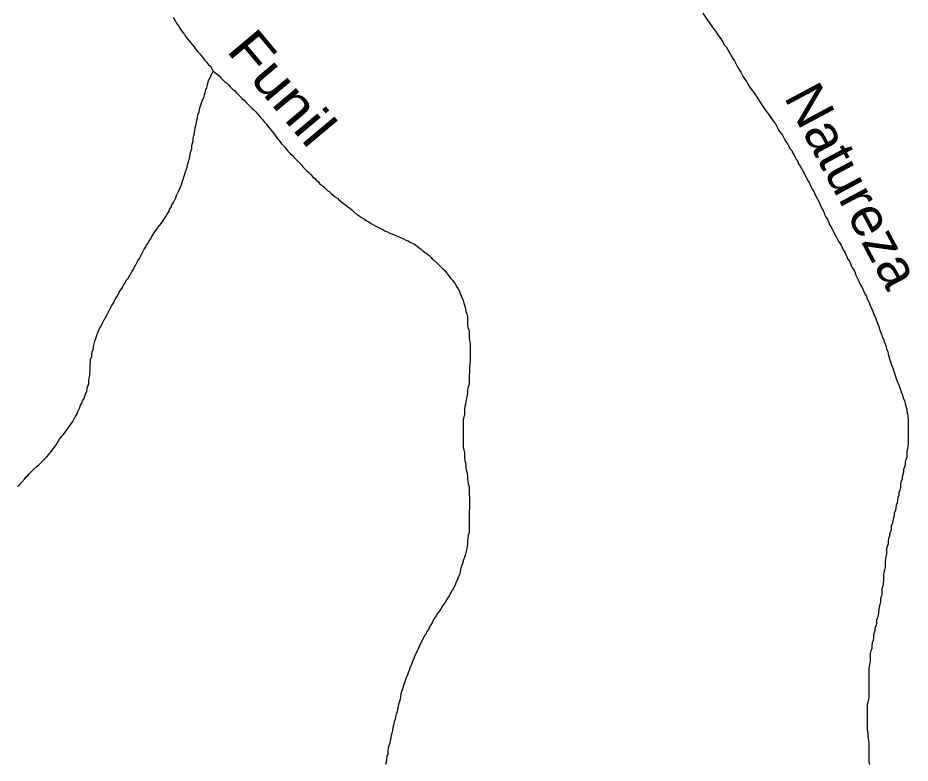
# Model space of a CAD drawing. Extents: x 652.3 to 678, y 7316.9 to 7344.9.
# Drawn here: x 663.889 to 665.722, y 7328.056 to 7329.588 of the extents above; entities that cross this region are included whole.
import ezdxf
from ezdxf.enums import TextEntityAlignment as Align

# ---------------------------------------------------------------- set-up
doc = ezdxf.new("R2010")
doc.units = 0
doc.header["$LTSCALE"] = 0.032
doc.layers.add('61', color=7, linetype='Continuous')
doc.layers.add('7', color=7, linetype='Continuous', lineweight=25)

msp = doc.modelspace()

# ---------------------------------------------------------------- linework, layer by layer
at = {"layer": '7'}
for points in [[(665.2961, 7329.5979), (665.3056, 7329.5836), (665.3088, 7329.5788), (665.312, 7329.574), (665.3152, 7329.57), (665.3184, 7329.5653), (665.3215, 7329.5613), (665.3279, 7329.5517), (665.3311, 7329.547), (665.3375, 7329.5374), (665.3398, 7329.5326), (665.3438, 7329.5287), (665.3462, 7329.5239), (665.3494, 7329.5191), (665.3518, 7329.5143), (665.355, 7329.5096), (665.3574, 7329.5048), (665.3605, 7329.5), (665.3653, 7329.4905), (665.3685, 7329.4857), (665.3709, 7329.4809), (665.3741, 7329.4769), (665.3788, 7329.4674), (665.382, 7329.4626), (665.3852, 7329.4578), (665.3876, 7329.4531), (665.394, 7329.4435), (665.3971, 7329.4387), (665.4003, 7329.4348), (665.4099, 7329.4204), (665.4131, 7329.4157), (665.4226, 7329.4014), (665.4258, 7329.3966), (665.429, 7329.3926), (665.4321, 7329.3886), (665.4353, 7329.3838), (665.4417, 7329.3743), (665.4449, 7329.3703), (665.4497, 7329.3608), (665.4528, 7329.356), (665.456, 7329.3512), (665.4592, 7329.3472), (665.464, 7329.3377), (665.4672, 7329.3329), (665.4703, 7329.3289), (665.4727, 7329.3242), (665.4751, 7329.3194), (665.4783, 7329.3154), (665.4799, 7329.3106), (665.4831, 7329.3067), (665.4878, 7329.2971), (665.491, 7329.2931), (665.4926, 7329.2884), (665.4958, 7329.2836), (665.4982, 7329.2788), (665.5014, 7329.274), (665.5038, 7329.2693), (665.5109, 7329.2549), (665.5141, 7329.2502), (665.5165, 7329.2454), (665.5181, 7329.2406), (665.5213, 7329.2358), (665.5237, 7329.2311), (665.526, 7329.2263), (665.5276, 7329.2215), (665.5308, 7329.2168), (665.5332, 7329.212)], [(664.2076, 7329.5899), (664.21, 7329.5852), (664.2132, 7329.5804), (664.2155, 7329.5756), (664.2187, 7329.5716), (664.2211, 7329.5669), (664.2243, 7329.5629), (664.2275, 7329.5581), (664.2307, 7329.5541), (664.2338, 7329.5493), (664.237, 7329.5454), (664.2402, 7329.5414), (664.2434, 7329.5374), (664.2466, 7329.5334), (664.2498, 7329.5295), (664.2529, 7329.5255), (664.2561, 7329.5215), (664.2593, 7329.5175), (664.2633, 7329.5135), (664.2665, 7329.5088), (664.2696, 7329.5048), (664.2728, 7329.5008), (664.2768, 7329.4968), (664.28, 7329.4921)], [(664.28, 7329.4921), (664.284, 7329.4889), (664.2895, 7329.4785)], [(664.2084, 7329.2088), (664.2132, 7329.2183), (664.2147, 7329.2231), (664.2195, 7329.2327), (664.2211, 7329.2374), (664.2235, 7329.2422), (664.2251, 7329.2478), (664.2267, 7329.2526), (664.2315, 7329.2669), (664.233, 7329.2717), (664.2362, 7329.2812), (664.237, 7329.2868), (664.2394, 7329.2923), (664.2402, 7329.2979), (664.2418, 7329.3027), (664.2426, 7329.3091), (664.2442, 7329.3138), (664.2458, 7329.3194), (664.2458, 7329.3258), (664.2474, 7329.3305), (664.249, 7329.3353), (664.249, 7329.3409), (664.2498, 7329.3464), (664.2513, 7329.3512), (664.2521, 7329.3568), (664.2529, 7329.3624), (664.2545, 7329.3671), (664.2553, 7329.3727), (664.2561, 7329.3783), (664.2577, 7329.3831), (664.2585, 7329.3894), (664.2609, 7329.3942), (664.2617, 7329.4006), (664.2633, 7329.4053), (664.2681, 7329.4197), (664.2704, 7329.4244), (664.272, 7329.43), (664.2736, 7329.4348), (664.2744, 7329.4403), (664.2768, 7329.4451), (664.2784, 7329.4507), (664.28, 7329.4594), (664.284, 7329.4674), (664.2895, 7329.4785)], [(664.2895, 7329.4785), (664.3023, 7329.469), (664.3055, 7329.465), (664.3094, 7329.461), (664.3134, 7329.4578), (664.3174, 7329.4547), (664.3214, 7329.4507), (664.3253, 7329.4459), (664.3293, 7329.4419), (664.3333, 7329.4387), (664.3373, 7329.4348), (664.3413, 7329.4308), (664.3452, 7329.4268), (664.3492, 7329.4228), (664.3532, 7329.4189), (664.3572, 7329.4149), (664.3612, 7329.4109), (664.3651, 7329.4069), (664.3691, 7329.4029), (664.3731, 7329.399), (664.3771, 7329.395), (664.381, 7329.391), (664.3842, 7329.387), (664.3874, 7329.3831), (664.3914, 7329.3791), (664.3946, 7329.3743), (664.3986, 7329.3703), (664.4017, 7329.3663), (664.4049, 7329.3624), (664.4081, 7329.3584), (664.4113, 7329.3544), (664.4145, 7329.3504), (664.4176, 7329.3457), (664.4208, 7329.3417), (664.424, 7329.3377), (664.4272, 7329.3337), (664.4304, 7329.3297), (664.4336, 7329.3258), (664.4375, 7329.3218), (664.4407, 7329.3178), (664.4439, 7329.3138), (664.4479, 7329.3098), (664.4519, 7329.3059), (664.4558, 7329.3019), (664.4598, 7329.2979), (664.4638, 7329.2939), (664.467, 7329.29), (664.471, 7329.286), (664.4741, 7329.282), (664.4781, 7329.278), (664.4821, 7329.274), (664.4861, 7329.2701), (664.4901, 7329.2661), (664.494, 7329.2621), (664.498, 7329.2589), (664.5012, 7329.2549), (664.5052, 7329.2518), (664.5084, 7329.2478), (664.5123, 7329.2446), (664.5163, 7329.2414), (664.5203, 7329.2374), (664.5243, 7329.2343), (664.5282, 7329.2311), (664.5322, 7329.2271), (664.5362, 7329.2239), (664.5402, 7329.2207), (664.545, 7329.2175), (664.5489, 7329.2136), (664.5537, 7329.2104), (664.5577, 7329.2064), (664.5625, 7329.2032), (664.5664, 7329.2), (664.5704, 7329.1969), (664.5744, 7329.1937), (664.5784, 7329.1905), (664.5824, 7329.1865), (664.5871, 7329.1833), (664.5919, 7329.1802), (664.5959, 7329.177), (664.6007, 7329.1746), (664.6046, 7329.1714), (664.6094, 7329.169), (664.6142, 7329.1658), (664.619, 7329.1626), (664.6237, 7329.1603), (664.6285, 7329.1579), (664.6333, 7329.1555), (664.6381, 7329.1531), (664.6428, 7329.1507), (664.6476, 7329.1483), (664.6524, 7329.1459), (664.6571, 7329.1443), (664.6619, 7329.142), (664.6667, 7329.1404), (664.6715, 7329.138), (664.6762, 7329.1364), (664.681, 7329.134), (664.6858, 7329.1316), (664.6906, 7329.13)], [(663.8885, 7328.6253), (663.8887, 7328.6256), (663.8909, 7328.6279), (663.902, 7328.6399), (663.9052, 7328.6439), (663.9092, 7328.6478), (663.9124, 7328.6518), (663.9164, 7328.6558), (663.9203, 7328.659), (663.9283, 7328.6669), (663.9323, 7328.6701), (663.9482, 7328.686), (663.9514, 7328.69), (663.9546, 7328.694), (663.9641, 7328.7059), (663.9673, 7328.7107), (663.9697, 7328.7155), (663.9729, 7328.7202), (663.9792, 7328.7282), (663.9824, 7328.7322), (663.9856, 7328.737), (663.9888, 7328.7417), (663.9983, 7328.7537), (664.0015, 7328.7584), (664.0063, 7328.768), (664.0095, 7328.7728), (664.011, 7328.7775), (664.0158, 7328.7871), (664.0174, 7328.7919), (664.0198, 7328.7966), (664.0214, 7328.8014), (664.0246, 7328.8062), (664.0262, 7328.811), (664.0278, 7328.8157), (664.0301, 7328.8205), (664.0309, 7328.8269), (664.0341, 7328.8364), (664.0341, 7328.842), (664.0349, 7328.8476), (664.0365, 7328.8531), (664.0365, 7328.8587), (664.0373, 7328.8643), (664.0373, 7328.8754), (664.0381, 7328.881), (664.0381, 7328.8865), (664.0405, 7328.8913), (664.0405, 7328.8969), (664.0413, 7328.9025), (664.0437, 7328.9072), (664.0437, 7328.9128), (664.0469, 7328.9239), (664.0484, 7328.9295), (664.05, 7328.9343), (664.0532, 7328.9438), (664.0556, 7328.9486), (664.058, 7328.9534), (664.0612, 7328.9582), (664.066, 7328.9677), (664.0683, 7328.9725), (664.0715, 7328.9772), (664.0763, 7328.9868), (664.0787, 7328.9916), (664.0811, 7328.9963), (664.0843, 7329.0011), (664.0866, 7329.0059), (664.089, 7329.0107), (664.0922, 7329.0146), (664.0946, 7329.0194), (664.097, 7329.0242), (664.1033, 7329.0337), (664.1057, 7329.0385), (664.1089, 7329.0433), (664.1113, 7329.0481), (664.1145, 7329.052), (664.1169, 7329.0568), (664.1201, 7329.0616), (664.1224, 7329.0664), (664.1256, 7329.0703), (664.1272, 7329.0751), (664.1304, 7329.0791), (664.1352, 7329.0886), (664.1384, 7329.0934), (664.1455, 7329.1077), (664.1479, 7329.1125), (664.1511, 7329.1165), (664.1527, 7329.1213), (664.1559, 7329.1252), (664.1583, 7329.13), (664.1614, 7329.134), (664.1638, 7329.1388), (664.1702, 7329.1483), (664.1734, 7329.1531), (664.1766, 7329.1579), (664.1829, 7329.1658), (664.1925, 7329.1802), (664.1956, 7329.1849), (664.1988, 7329.1897), (664.2004, 7329.1945), (664.2036, 7329.1992), (664.2052, 7329.204), (664.2084, 7329.2088)], [(665.5332, 7329.212), (665.5356, 7329.2072), (665.5372, 7329.2024), (665.5396, 7329.1977), (665.5427, 7329.1921), (665.5451, 7329.1873), (665.5467, 7329.1825), (665.5491, 7329.1778), (665.5523, 7329.173), (665.5547, 7329.1674), (665.5563, 7329.1626), (665.5595, 7329.1587), (665.5666, 7329.1443), (665.569, 7329.1396), (665.5738, 7329.13), (665.577, 7329.1252), (665.5801, 7329.1213), (665.5817, 7329.1165), (665.5841, 7329.1117), (665.5873, 7329.1069), (665.5897, 7329.1022), (665.5913, 7329.0974), (665.5937, 7329.0926), (665.5969, 7329.0879), (665.5992, 7329.0831), (665.6008, 7329.0783), (665.6032, 7329.0735), (665.6064, 7329.0688), (665.6088, 7329.064), (665.6104, 7329.0592), (665.6152, 7329.0497), (665.6167, 7329.0449), (665.6191, 7329.0401), (665.6223, 7329.0353), (665.6247, 7329.0306), (665.6263, 7329.0258), (665.6287, 7329.021), (665.6319, 7329.0154), (665.6335, 7329.0107), (665.6358, 7329.0059), (665.6382, 7329.0011), (665.6398, 7328.9963), (665.6422, 7328.9916), (665.6446, 7328.9868), (665.6478, 7328.9772), (665.6502, 7328.9725), (665.6518, 7328.9677), (665.6541, 7328.9629), (665.6573, 7328.9534), (665.6589, 7328.9486), (665.6605, 7328.943), (665.6629, 7328.9383), (665.6645, 7328.9327), (665.6669, 7328.9279), (665.6685, 7328.9231), (665.6701, 7328.9176), (665.6724, 7328.9128), (665.6732, 7328.9072), (665.6756, 7328.9025), (665.6764, 7328.8969), (665.678, 7328.8921), (665.6796, 7328.8873), (665.6844, 7328.873), (665.686, 7328.8682), (665.6907, 7328.8539), (665.6923, 7328.8491), (665.6955, 7328.8396), (665.6987, 7328.834), (665.7035, 7328.8197), (665.7051, 7328.8149), (665.7083, 7328.8054), (665.7106, 7328.8006), (665.7114, 7328.795), (665.713, 7328.7903), (665.7146, 7328.7847), (665.7146, 7328.7791), (665.7162, 7328.7743), (665.717, 7328.7688), (665.7178, 7328.7632), (665.7178, 7328.7131), (665.717, 7328.7075), (665.7162, 7328.7019), (665.7146, 7328.6972), (665.7146, 7328.6852), (665.713, 7328.6805), (665.7114, 7328.6749), (665.7114, 7328.6693), (665.7098, 7328.6645), (665.7083, 7328.6598), (665.7083, 7328.6542), (665.7067, 7328.6494), (665.7051, 7328.6447), (665.7051, 7328.6391), (665.7027, 7328.6343), (665.7019, 7328.6287), (665.7019, 7328.6232), (665.7003, 7328.6176), (665.6987, 7328.6128), (665.6987, 7328.6073), (665.6963, 7328.6025), (665.6955, 7328.5969)], [(664.6906, 7329.13), (664.6953, 7329.1268), (664.7001, 7329.1252), (664.7041, 7329.1221), (664.7089, 7329.1189), (664.7128, 7329.1157), (664.7168, 7329.1125), (664.7208, 7329.1093), (664.7248, 7329.1062), (664.7296, 7329.103), (664.7335, 7329.0998), (664.7375, 7329.0958), (664.7407, 7329.0918), (664.7455, 7329.0886), (664.7494, 7329.0847), (664.7534, 7329.0807), (664.7574, 7329.0767), (664.7614, 7329.0727), (664.7654, 7329.0688), (664.7685, 7329.0648), (664.7717, 7329.0608), (664.7749, 7329.0568), (664.7781, 7329.0528), (664.7813, 7329.0489), (664.7845, 7329.0449), (664.7876, 7329.0409), (664.79, 7329.0361), (664.7932, 7329.0314), (664.7956, 7329.0266), (664.7972, 7329.0218), (664.7996, 7329.017), (664.8012, 7329.0123), (664.8036, 7329.0075), (664.8051, 7329.0019), (664.8067, 7328.9956), (664.8083, 7328.9908), (664.8091, 7328.9844), (664.8107, 7328.9796), (664.8123, 7328.9741), (664.8123, 7328.9685), (664.8123, 7328.9629), (664.8123, 7328.9574), (664.8131, 7328.9518), (664.8147, 7328.947), (664.8155, 7328.9414), (664.8155, 7328.9359), (664.8155, 7328.9303), (664.8163, 7328.9247), (664.8179, 7328.9192), (664.8179, 7328.9136), (664.8179, 7328.908), (664.8179, 7328.9025), (664.8179, 7328.8969), (664.8179, 7328.8881), (664.8179, 7328.8826), (664.8171, 7328.877), (664.8163, 7328.8714), (664.8163, 7328.8659), (664.8163, 7328.8603), (664.8155, 7328.8547), (664.8155, 7328.8491), (664.8155, 7328.8436), (664.8155, 7328.838), (664.8147, 7328.8324), (664.8131, 7328.8277), (664.8123, 7328.8221), (664.8123, 7328.8157), (664.8107, 7328.811), (664.8099, 7328.8054), (664.8091, 7328.7998), (664.8083, 7328.7942), (664.8067, 7328.7895), (664.8059, 7328.7839), (664.8059, 7328.7783), (664.8059, 7328.7728), (664.8051, 7328.7672), (664.8036, 7328.7624), (664.8036, 7328.7568), (664.8036, 7328.7513), (664.8036, 7328.7457), (664.8036, 7328.7385), (664.8036, 7328.733), (664.8036, 7328.7274), (664.8036, 7328.7218), (664.8036, 7328.7163), (664.8036, 7328.7107), (664.8036, 7328.7051), (664.8051, 7328.7003), (664.8059, 7328.6948), (664.8059, 7328.6892), (664.8059, 7328.6836), (664.8067, 7328.6781), (664.8083, 7328.6733), (664.8091, 7328.6677), (664.8091, 7328.6622), (664.8099, 7328.6566), (664.8115, 7328.6518), (664.8123, 7328.6462), (664.8123, 7328.6407), (664.8131, 7328.6351), (664.8139, 7328.6295)], [(664.8139, 7328.6295), (664.8155, 7328.6248), (664.8155, 7328.6192), (664.8155, 7328.6136), (664.8155, 7328.6081), (664.8163, 7328.6025), (664.8163, 7328.5969), (664.8163, 7328.5913), (664.8163, 7328.5858), (664.8163, 7328.5802), (664.8155, 7328.5746), (664.8155, 7328.5691), (664.8155, 7328.5635), (664.8155, 7328.5579), (664.8155, 7328.5524), (664.8155, 7328.5468), (664.8155, 7328.5412), (664.8155, 7328.5356), (664.8155, 7328.5301), (664.8139, 7328.5245), (664.8131, 7328.5189), (664.8123, 7328.5134), (664.8123, 7328.5078), (664.8115, 7328.5014), (664.8099, 7328.4951), (664.8091, 7328.4895), (664.8075, 7328.4839), (664.8059, 7328.4791), (664.8044, 7328.4744), (664.8028, 7328.4696), (664.8012, 7328.4648), (664.7996, 7328.4601), (664.798, 7328.4545), (664.7972, 7328.4489), (664.7956, 7328.4433), (664.7932, 7328.4386), (664.7916, 7328.4338), (664.7892, 7328.429), (664.7876, 7328.4242), (664.7853, 7328.4195), (664.7829, 7328.4147), (664.7797, 7328.4099), (664.7773, 7328.4051), (664.7749, 7328.4004), (664.7717, 7328.3964), (664.7693, 7328.3916), (664.7662, 7328.3868), (664.763, 7328.3821), (664.7598, 7328.3773), (664.7574, 7328.3725), (664.7542, 7328.3685), (664.751, 7328.3638), (664.7479, 7328.359), (664.7447, 7328.3542), (664.7415, 7328.3495), (664.7399, 7328.3447), (664.7367, 7328.3407), (664.7343, 7328.3359), (664.7319, 7328.3312), (664.7288, 7328.3272), (664.7272, 7328.3224), (664.724, 7328.3184), (664.7216, 7328.3136), (664.7192, 7328.3089), (664.7168, 7328.3041), (664.7144, 7328.2993), (664.7121, 7328.2945), (664.7105, 7328.2898), (664.7081, 7328.285), (664.7057, 7328.2802), (664.7033, 7328.2755), (664.7017, 7328.2707), (664.6993, 7328.2659), (664.6977, 7328.2611), (664.6961, 7328.2564), (664.6938, 7328.2516), (664.6922, 7328.2468), (664.6906, 7328.242), (664.689, 7328.2373), (664.6866, 7328.2325), (664.685, 7328.2277), (664.6834, 7328.2229), (664.6818, 7328.2182), (664.6802, 7328.2134), (664.6786, 7328.2086), (664.677, 7328.2038), (664.6754, 7328.1991), (664.6747, 7328.1935), (664.6739, 7328.1879), (664.6723, 7328.1832), (664.6707, 7328.1776), (664.6699, 7328.172), (664.6683, 7328.1672), (664.6675, 7328.1617), (664.6659, 7328.1569), (664.6643, 7328.1513), (664.6635, 7328.1458), (664.6619, 7328.141), (664.6603, 7328.1346), (664.6587, 7328.1298), (664.6579, 7328.1235)], [(665.6955, 7328.5969), (665.6947, 7328.5913), (665.6931, 7328.5866), (665.6923, 7328.581), (665.6915, 7328.5754), (665.6892, 7328.5707), (665.6892, 7328.5651), (665.6876, 7328.5603), (665.686, 7328.5547), (665.6852, 7328.5492), (665.6828, 7328.5444), (665.6828, 7328.5388), (665.682, 7328.5333), (665.6796, 7328.5285), (665.6796, 7328.5229), (665.6772, 7328.5181), (665.6764, 7328.5126), (665.6764, 7328.507), (665.6732, 7328.4974), (665.6732, 7328.4863), (665.6717, 7328.4807), (665.6709, 7328.4752), (665.6701, 7328.4696), (665.6701, 7328.4585), (665.6693, 7328.4529), (665.6677, 7328.4481), (665.6669, 7328.4425), (665.6669, 7328.4314), (665.6653, 7328.4203), (665.6637, 7328.4147), (665.6637, 7328.4036), (665.6621, 7328.398), (665.6605, 7328.3932), (665.6605, 7328.3876), (665.6597, 7328.3821), (665.6581, 7328.3773), (665.6573, 7328.3717), (665.6557, 7328.3606), (665.6549, 7328.355), (665.6526, 7328.3502), (665.6526, 7328.3447), (665.6518, 7328.3391), (665.6494, 7328.3343), (665.6494, 7328.3288), (665.6462, 7328.3192), (665.6462, 7328.3136), (665.6454, 7328.3081), (665.6438, 7328.3033), (665.643, 7328.2977), (665.643, 7328.2922), (665.6406, 7328.2874), (665.6398, 7328.2818), (665.6398, 7328.2651), (665.6382, 7328.2595), (665.6366, 7328.2484), (665.6366, 7328.1927), (665.6358, 7328.1871), (665.635, 7328.1816), (665.6335, 7328.1768), (665.6335, 7328.1267), (665.6343, 7328.1211), (665.635, 7328.1155), (665.635, 7328.1099), (665.6358, 7328.1044), (665.6366, 7328.0988), (665.6366, 7328.0598), (665.6382, 7328.0535)], [(664.6579, 7328.1235), (664.6571, 7328.1179), (664.6556, 7328.1131), (664.6548, 7328.1076), (664.6532, 7328.1028), (664.6524, 7328.0972), (664.6508, 7328.0916), (664.6492, 7328.0869), (664.6484, 7328.0805), (664.6484, 7328.0749), (664.6468, 7328.0702), (664.646, 7328.0646), (664.6452, 7328.0582), (664.6436, 7328.0535)]]:
    msp.add_lwpolyline(points, dxfattribs=at)

# ---------------------------------------------------------------- texts
at = {"layer": '61'}
for s, rotation, width, p in [('Funil', 310.031, 1.15, (664.4009, 7329.4188)), ('Natureza', 298.088, 1.05, (665.5687, 7329.2249))]:
    msp.add_text(s, height=0.08, rotation=rotation, dxfattribs=dict(at, width=width)).set_placement(p, align=Align.CENTER)

doc.saveas('drawing.dxf')
